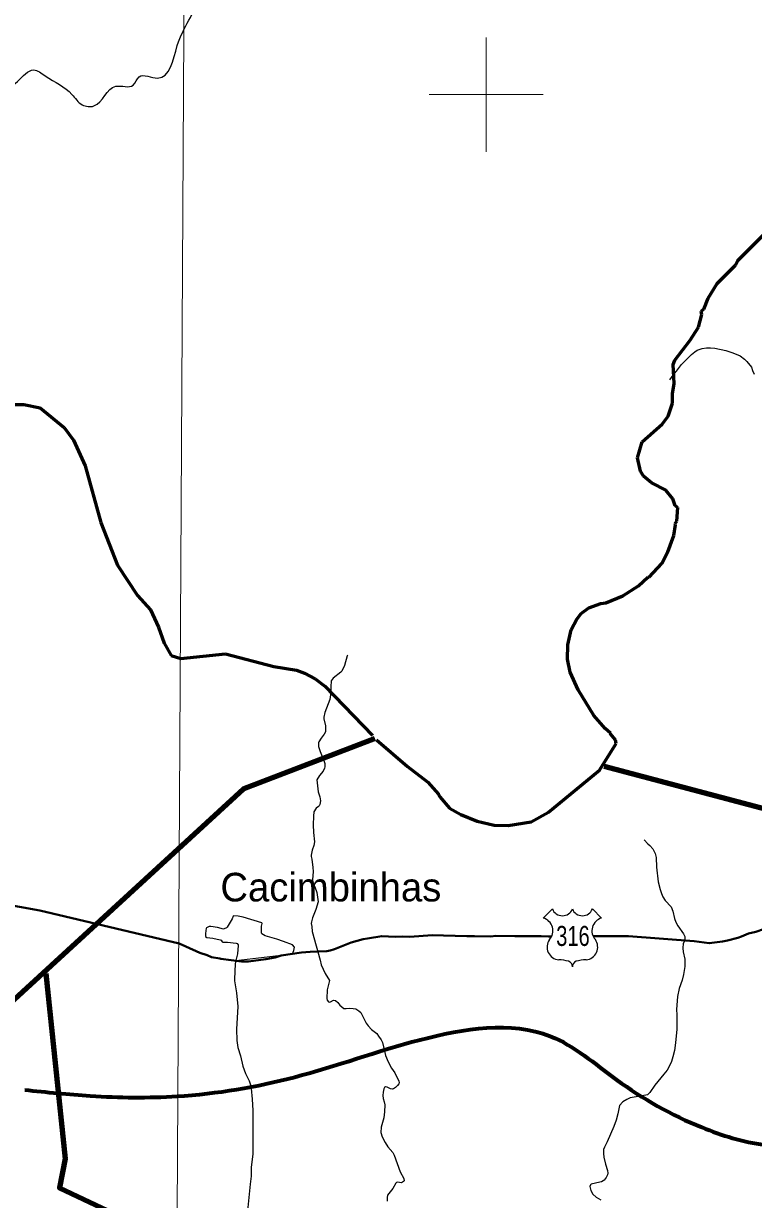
# Model space of a CAD drawing. Extents: x 553962 to 842807, y 8883888 to 9032388.
# Drawn here: x 716906 to 729677, y 8955681 to 8976242 of the extents above; entities that cross this region are included whole.
import ezdxf
from ezdxf.enums import TextEntityAlignment as Align

# ---------------------------------------------------------------- set-up
doc = ezdxf.new("R2010")
doc.units = 0
doc.header["$LTSCALE"] = 200
doc.linetypes.add('LONG_DASH_SHORT_DASH', pattern=[9.9, 6, -1.2, 1.5, -1.2])
for name, color, linetype, lineweight in [('1', 7, 'Continuous', 13), ('12', 7, 'Continuous', 25), ('2', 7, 'Continuous', 13), ('21', 7, 'Continuous', 25), ('24', 7, 'Continuous', 25), ('48', 7, 'Continuous', 25), ('51', 7, 'Continuous', 70), ('7', 7, 'LONG_DASH_SHORT_DASH', 60), ('9', 7, 'Continuous', 90)]:
    doc.layers.add(name, color=color, linetype=linetype, lineweight=lineweight)
doc.layers.add('41', color=7, linetype='Continuous')

msp = doc.modelspace()

# ---------------------------------------------------------------- linework, layer by layer
at = {"layer": '1'}
msp.add_lwpolyline([(719978.9, 9023574.5), (719561.6, 8949232.2), (719215.6, 8890710.6)], dxfattribs=at)
at = {"layer": '12', "lineweight": 40}
for points in [[(710551.5, 8961397.1), (711177.1, 8961501.2), (712016, 8961727.1), (712359, 8961724.2), (713550.7, 8961508.2), (716056.5, 8960938), (717193.5, 8960736.2), (719630.3, 8960157.3)], [(727488.2, 8960282.3), (728636.4, 8960199.6), (728903.4, 8960161.8), (729137.1, 8960189.3), (729219.7, 8960208.1), (729401, 8960258.8), (729465.4, 8960280.4), (729590.6, 8960330), (729719.4, 8960363), (729852.5, 8960406), (729969, 8960418.2), (730064.3, 8960434.8), (730362.8, 8960475.9), (730505.9, 8960510.9), (731000.5, 8960614.4), (731116.1, 8960622.6), (731172.1, 8960636.4), (731339.7, 8960662.3), (731644.2, 8960700.6)], [(721922.9, 8960009), (722213.7, 8960025.4), (722269.8, 8960036.4), (722349.1, 8960058.4), (722636.1, 8960173.1), (722845.7, 8960234.4), (722922.5, 8960243.5), (723174, 8960287.2), (723408.1, 8960273.8), (723541.7, 8960277.9), (723662.4, 8960276.1), (724053.4, 8960301.3), (724251.5, 8960299.1), (724661.8, 8960282.6), (724797.4, 8960284.4), (725081.1, 8960280.5), (725171.8, 8960288.1), (725504.3, 8960282.4), (725962.1, 8960286.2), (726091.1, 8960280.3), (726144.9, 8960281.9)], [(726871.4, 8960282.4), (727184.2, 8960282.3), (727488.2, 8960282.3)], [(719630.3, 8960157.3), (719924.9, 8960025), (719991.1, 8959995.2), (720116.1, 8959954.9), (720192.2, 8959919.6), (720337.5, 8959893.8), (720356.6, 8959891.3)], [(721309.9, 8959913.9), (721410.9, 8959945.9), (721766.8, 8959996.8), (721847.5, 8960004.7), (721922.9, 8960009)], [(720356.6, 8959891.3), (720717.1, 8959843.9), (720842.5, 8959844.2), (721142.7, 8959881.7), (721309.9, 8959913.9)]]:
    msp.add_lwpolyline(points, dxfattribs=at)
at = {"layer": '12'}
msp.add_lwpolyline([(720615.2, 8959855.5), (720600.9, 8959695.2), (720597, 8959505.1), (720630.5, 8959292.2), (720652.8, 8959055), (720632.1, 8958659.5), (720635, 8958462), (720656.1, 8958337.2), (720700.8, 8958191.8), (720743.2, 8958010.9), (720791.1, 8957885.8), (720852.6, 8957752.9), (720877.2, 8957688.2), (720888, 8957623.8), (720908.9, 8957434.4), (720919.8, 8957236.9), (720915.8, 8956822.8), (720917.5, 8956475.5), (720890.2, 8956243.7), (720885.8, 8956166.3), (720886.8, 8956088.9), (720868.9, 8955947.1), (720826.5, 8955484.8)], dxfattribs=at)
at = {"layer": '2'}
for p, q in [((725000, 8974000), (725000, 8976000)), ((724000, 8975000), (726000, 8975000))]:
    msp.add_line(p, q, dxfattribs=at)
at = {"layer": '21'}
for points in [[(721081.2, 8960508.1), (721077.4, 8960519.1), (720747.7, 8960615.2), (720662.9, 8960634.1), (720587.2, 8960643), (720575.8, 8960636.9), (720556, 8960586.9), (720470.6, 8960443.6), (720458.9, 8960430), (720418.1, 8960410.7), (720402.2, 8960408.3), (720301.9, 8960437.2), (720181, 8960453.2), (720156.1, 8960451.2), (720109.1, 8960428.1), (720098.9, 8960418.5), (720097.9, 8960382.4), (720087.7, 8960324.8), (720086.7, 8960296.8), (720091.3, 8960280.8), (720111.5, 8960263.6), (720216.2, 8960251.9), (720344.2, 8960222.5), (720362.4, 8960214), (720382.8, 8960188), (720394.4, 8960180.7), (720474.7, 8960182.3), (720628.9, 8960163.3), (720641.9, 8960157.8), (720658.4, 8960133.9), (720662.8, 8960119.5), (720650.8, 8959977.9), (720618.4, 8959856.9), (721612.4, 8959974.7)], [(721612.4, 8959974.7), (721632.5, 8960032.7), (721644.1, 8960093.2), (721614, 8960131.4), (721452.9, 8960193.9), (721340.2, 8960231.7), (721132.5, 8960290.7), (721078, 8960323.4), (721072, 8960337.7), (721069.2, 8960462.3), (721081.2, 8960508.1)]]:
    msp.add_lwpolyline(points, dxfattribs=at)
at = {"layer": '24'}
for points in [[(728214.3, 8970014.3), (728272, 8970092.8), (728331.6, 8970162.7), (728417.4, 8970282.5), (728594.8, 8970457.4), (728648.4, 8970499.8), (728691.9, 8970528.1), (728779.9, 8970559.1)], [(728779.9, 8970559.1), (728852.1, 8970572.7), (728924.3, 8970573), (729000.6, 8970564.2), (729191.8, 8970527), (729315.4, 8970483.8), (729446.4, 8970430), (729519.7, 8970374), (729562.9, 8970331.7), (729643.8, 8970234.4), (729657.8, 8970174.1), (729686.6, 8970110.8)], [(722575.5, 8965195.4), (722571, 8965187.9), (722519, 8965016.7), (722474.9, 8964918.2), (722459.2, 8964901.6), (722323.5, 8964797.9), (722290.5, 8964747.2), (722279.7, 8964646.8), (722281, 8964566), (722277.5, 8964502.2), (722266.5, 8964421.5), (722176.2, 8964195.9), (722157.5, 8964115.2), (722160.4, 8964087.6), (722187, 8963962.1), (722189.1, 8963859.1), (722167.7, 8963817.5), (722110.5, 8963747.7), (722070.3, 8963681.7), (722063.8, 8963664.4), (722068.1, 8963601.1), (722094, 8963516.1), (722162.6, 8963358.1), (722176.2, 8963303.1), (722177, 8963244), (722173.6, 8963223), (722150.4, 8963167.1), (722082.2, 8963092.3), (722039.2, 8963018), (722060.5, 8962810.2), (722090.5, 8962720.7), (722103.1, 8962648.5), (722089.6, 8962588.8), (722078.8, 8962562.8), (722066.8, 8962550.6), (722025.2, 8962521.8), (721986.8, 8962458), (721978, 8962385), (721975.3, 8962231.7), (721979, 8962096), (721995.3, 8961934.2), (721985.8, 8961870.2), (721954.4, 8961789.1)], [(727765.8, 8961970.3), (727825.8, 8961899), (727865.1, 8961870.8), (727914.4, 8961812.9), (727928.9, 8961790.8), (727957, 8961730.6), (727973.7, 8961658.3), (727982.1, 8961491.7), (728008.3, 8961232.6), (728042.5, 8961100.9), (728042.5, 8961100.9)], [(721954.4, 8961789.1), (721939, 8961701.5), (721940.5, 8961675.6), (721951.9, 8961632), (721968.9, 8961483.5), (721970.5, 8961415.5), (721961.3, 8961271), (721974.8, 8961199.1), (722002.5, 8961147.9), (722036.1, 8961049.7), (722059, 8960887.1), (722022.2, 8960752.4), (721958.8, 8960603.3), (721941.3, 8960535.4), (721939.8, 8960504.4), (721952, 8960451.2), (721953.6, 8960363.9)], [(728042.5, 8961100.9), (728066.8, 8961029.4), (728091.6, 8960973.5), (728132.1, 8960907.8), (728236.6, 8960797.5), (728265.1, 8960722.4), (728295.7, 8960595), (728319, 8960531.3), (728352.9, 8960467.6), (728449.6, 8960324.9), (728474.6, 8960281.8), (728477.4, 8960259.1), (728473.9, 8960208), (728448.7, 8960159), (728438.4, 8960076.1), (728447.6, 8960012.3), (728475.3, 8959880.6), (728477.7, 8959816.9), (728475.3, 8959753.2), (728452.1, 8959613.4), (728430.3, 8959518.6), (728374.1, 8959370.4), (728347.8, 8959231.5), (728331.8, 8959004.4), (728331.8, 8959004.4), (728335.5, 8958911.7), (728334.3, 8958656.7), (728310.4, 8958418), (728292.8, 8958286.4), (728267.6, 8958175.1), (728241.7, 8958095.1), (728211.8, 8958027.2), (728164.6, 8957944.8), (728110.8, 8957873.6), (728053, 8957810), (727953.2, 8957682.5), (727865.8, 8957554.2), (727836.3, 8957521.6), (727822.7, 8957513.3), (727793.9, 8957504.8), (727522, 8957455.7), (727461.9, 8957429.1), (727393.2, 8957387.5), (727330.4, 8957324.7), (727300.9, 8957176.3), (727274.3, 8957069.5), (727235.3, 8956955.2), (727115.7, 8956689.6), (727067.7, 8956593.8), (727054.2, 8956553.9), (727051.8, 8956483.4), (727060.3, 8956419.9), (727085.9, 8956300.9), (727122.2, 8956185.9), (727127.8, 8956143.5), (727122.6, 8956114.6), (727099.9, 8956065), (727062.7, 8956016.1), (727045.7, 8956009.6), (727016.4, 8955987.1), (726986.5, 8955986.3)], [(721953.6, 8960363.9), (722093.6, 8959865.1), (722115.4, 8959783), (722181.9, 8959629.9), (722261.1, 8959510.9)], [(722261.1, 8959510.9), (722232.9, 8959419.5), (722220.1, 8959349.1), (722211.4, 8959197.2), (722220.3, 8959168.5), (722243.5, 8959138), (722256, 8959132), (722279.2, 8959136), (722330.7, 8959164.3), (722365.7, 8959160.8), (722402.2, 8959127.6), (722442.3, 8959076.5), (722509.3, 8959021.4), (722549.7, 8959017.6), (722615.2, 8959023.5), (722670.4, 8959021.7), (722718.1, 8959012.5), (722774.8, 8958976.9), (722805.5, 8958948), (722900.4, 8958766.3), (722936.6, 8958715.7), (722995.9, 8958654.5), (723087, 8958581.5), (723116.2, 8958534.7)], [(723116.2, 8958534.7), (723162.6, 8958473.2), (723183.6, 8958425.5), (723238.3, 8958197.1), (723282.7, 8958086.6), (723342.1, 8957976.2), (723399.4, 8957895.1), (723474.7, 8957752.1), (723479.7, 8957724.8), (723473.3, 8957704.3), (723449.9, 8957676.3), (723412.8, 8957642), (723376.2, 8957617.7), (723360.7, 8957612.8), (723327.5, 8957613.9), (723266.1, 8957642.9), (723240.8, 8957648.2), (723221.2, 8957638.1), (723207.2, 8957613.1), (723195.8, 8957555.1), (723193.7, 8957499.8), (723199.5, 8957448.4), (723216.1, 8957389.2), (723224.3, 8957337.8), (723222.4, 8957215.7), (723211.1, 8957109.1), (723161.2, 8956943.2), (723155.2, 8956854.5), (723178.4, 8956777.7), (723231.8, 8956676.2), (723280.5, 8956599.2), (723364.6, 8956500.5), (723389.3, 8956454.5), (723495.1, 8956163.2), (723557.2, 8956045.2), (723565.7, 8956009), (723554.2, 8955994.3)], [(723554.2, 8955994.3), (723554.2, 8955994.3), (723519.5, 8955974.1), (723447.7, 8955984.5), (723432.7, 8955980), (723418, 8955965.8), (723364.6, 8955871.3), (723272.5, 8955754.9), (723268.2, 8955716.3), (723268.6, 8955650.3)], [(726986.5, 8955986.3), (726837.9, 8955949.1), (726825, 8955939.5), (726814.2, 8955910.4), (726817.4, 8955886), (726830.9, 8955839.7), (726865, 8955775.8), (726924.5, 8955721.1), (727005.9, 8955674.6)]]:
    msp.add_lwpolyline(points, dxfattribs=at)
msp.add_spline([(715037, 8973071.8), (715705.1, 8973746.2), (715968.5, 8974273.5), (716313.1, 8974881.9), (716799.5, 8975226.6), (717083.2, 8975429.4), (717285.9, 8975328), (717752, 8975003.5), (717934.4, 8974821), (718137.1, 8974800.7), (718522.2, 8975145.5), (718826.2, 8975165.8), (718927.5, 8975307.7), (719251.8, 8975287.5), (719596.3, 8975855.3), (719799, 8976301.5), (720042.2, 8976686.8), (720771.8, 8977072.1), (721197.4, 8977051.8), (721481.2, 8977356), (721987.8, 8977396.6), (722291.8, 8977356), (722514.8, 8977639.9), (722859.3, 8978086.1), (723244.4, 8978309.2), (723548.4, 8978795.9), (723507.9, 8979566.5), (723426.8, 8979749.1), (723730.8, 8980235.8), (724115.9, 8980418.3), (724501, 8980803.6), (724886, 8981067.2), (724886, 8981594.5), (724865.8, 8981939.3), (725068.4, 8982385.5), (725169.8, 8982831.6), (725331.9, 8983216.9), (725311.6, 8983582), (725473.8, 8983825.3), (725696.7, 8983987.6), (725777.8, 8984433.7), (725858.8, 8984636.5), (726183.1, 8984636.5), (726162.8, 8984920.5), (726284.5, 8985163.8), (726588.5, 8985569.4), (726993.8, 8986056.1), (726770.9, 8986299.5), (726466.9, 8986238.7), (726264.2, 8986340.1), (726527.7, 8986563.1), (726487.1, 8986745.7), (726770.9, 8986907.9), (727155.9, 8987090.4), (727297.8, 8987171.5), (727338.3, 8987496), (727581.6, 8987698.8), (727743.7, 8987921.9), (727905.8, 8988084.1), (728068, 8988408.6), (728351.7, 8988510), (728453, 8988814.2), (728655.7, 8988854.8), (728676, 8989098.1), (728898.9, 8989260.4), (729121.8, 8989260.4), (729284, 8989037.3), (729527.2, 8988733.1), (729750.1, 8988712.8), (729973.1, 8988834.5), (729993.3, 8988753.4), (730054.1, 8988530.3), (730135.2, 8988469.4), (730358.1, 8988469.4), (730459.5, 8988408.6), (730702.7, 8988489.7), (730702.7, 8988611.4), (730885.1, 8988652), (731067.5, 8988469.4), (731168.8, 8988347.8), (731472.8, 8988368), (731736.3, 8988631.7), (731857.9, 8988834.5), (732222.7, 8988814.2), (732324, 8989017), (732506.4, 8989138.7), (732547, 8989300.9), (732851, 8989402.3), (733073.9, 8989382), (733114.4, 8989666), (733215.8, 8989848.5)], degree=3, dxfattribs=at)
at = {"layer": '48'}
for p, q in [((725998.7, 8960602), (726158.6, 8960761.9)), ((726857.9, 8960761.9), (727017.9, 8960602))]:
    msp.add_line(p, q, dxfattribs=at)
for centre, radius, start, end in [((726333.4, 8960828.9), 187.2, 200.95927, 339.04073), ((726683.1, 8960828.9), 187.2, 200.95927, 339.04073), ((725936.6, 8960380.1), 230.3, 317.5721, 74.36886), ((727079.9, 8960380.1), 230.3, 105.62774, 222.4279), ((726290.1, 8960095), 224.7, 144.73733, 264.65778), ((726726.4, 8960095), 224.7, 275.34222, 35.26267), ((726268.2, 8959281.5), 589.7, 72.89371, 89.90057), ((726413.9, 8959754.9), 94.4, 357.69345, 72.92955), ((726602.6, 8959754.9), 94.4, 107.07045, 182.30655), ((726748.4, 8959281.5), 589.7, 90.09943, 107.10629)]:
    msp.add_arc(centre, radius, start, end, dxfattribs=at)
at = {"layer": '51'}
msp.add_spline([(716926.2, 8957598.1), (718074.6, 8957493.8), (719594.6, 8957486.8), (721652.8, 8957821.8), (723844.6, 8958473.8), (726122.5, 8958536.9), (727274.9, 8957780.4), (728772.1, 8956943.2), (729868.6, 8956635.9), (731465.1, 8956666.3)], degree=3, dxfattribs=at)
at = {"layer": '7'}
for points in [[(728775.4, 8971157.2), (728762.8, 8971215.3), (728807.7, 8971247.8), (728882.9, 8971442.9), (729041.4, 8971697.8), (729364.5, 8972018.1), (729404.2, 8972096.7), (730321.7, 8973018.8)], [(719658.3, 8965140.1), (720442, 8965220.3), (721288, 8965002.1), (721680.5, 8964933.5), (721820.1, 8964881.9), (722005.8, 8964784.1), (722178.5, 8964657), (723083.4, 8963715.2), (723625.8, 8963254.3), (723977.8, 8962977.1), (724168.2, 8962768.7), (724186.8, 8962722.9), (724359.5, 8962523.2), (724559.4, 8962414.2), (724841.1, 8962296.1), (725141, 8962223.5), (725386.8, 8962222.5), (725788.6, 8962283.2), (726090.3, 8962454.2), (726984.4, 8963189.7), (727272.9, 8963654), (727265.1, 8963720.5), (727171.4, 8963825.9), (727177.2, 8963835.7), (727083.5, 8963916.6), (726881.4, 8964145.8), (726607, 8964591.8), (726472.1, 8964903.4), (726424.9, 8965128.6), (726428, 8965378.3), (726489.2, 8965641.2), (726585.3, 8965827.1), (726663.7, 8965928.8), (726797, 8966026.6), (727004.8, 8966100.9), (727095.2, 8966112.8), (727389.2, 8966234.1), (727665.8, 8966411.4), (727830.4, 8966559.9), (727853.4, 8966559.4), (728073.8, 8966803.2), (728177.3, 8967005.8), (728281, 8967292.8), (728314.3, 8967479.3), (728306, 8967500.6), (728333.7, 8967541.7), (728350.7, 8967781.6), (728305.9, 8967811.8), (728268.5, 8967931), (728143.1, 8968083.6), (727891.6, 8968208.7), (727752.6, 8968328.3), (727699.6, 8968412.7), (727644.7, 8968647.4), (727727.1, 8968929.1), (728078.2, 8969238.6), (728184.2, 8969376), (728262.5, 8969602.8), (728262.6, 8969767.2), (728287.9, 8969948.7), (728268.9, 8970282.4), (728302.9, 8970356.4), (728566.6, 8970704.3), (728713.2, 8970930.1), (728775.4, 8971157.2)], [(714387.4, 8969902.2), (714562.6, 8969724), (714791.2, 8969580.7), (715019.8, 8969437.3), (715266.3, 8969329.2), (715566.5, 8969291.3), (716240, 8969497.5), (716452.6, 8969548.7), (716647.3, 8969582.3), (716912.5, 8969580.1), (717194.9, 8969524.6), (717616.1, 8969176.7), (717779.5, 8968954.6), (717981.6, 8968510.6), (718255.9, 8967518.7), (718550, 8966774), (718899, 8966240.8), (719126.6, 8965991.5), (719265.4, 8965689.9), (719369.1, 8965406.3), (719491, 8965193.2), (719658.3, 8965140.1)]]:
    msp.add_lwpolyline(points, dxfattribs=at)
at = {"layer": '9'}
msp.add_line((738230.2, 8960292.9), (727062.8, 8963254.1), dxfattribs=at)
for points in [[(705081.2, 8958366.8), (705509.2, 8948874.2), (720755.9, 8962863.6), (723053.6, 8963740.6)], [(717295.3, 8959630.3), (717636.9, 8956393.6), (717537.2, 8955887), (718376.1, 8955487), (718808.6, 8955185.8), (719472.1, 8954177.6), (719984.6, 8952814.2), (721077.3, 8952390.4), (721486.8, 8951456.6), (721666.8, 8950799.8), (721718.4, 8950547.1), (727920.4, 8947850.3), (733274.5, 8948007.9), (737635.8, 8948628.8)]]:
    msp.add_lwpolyline(points, dxfattribs=at)

# ---------------------------------------------------------------- texts
at = {"layer": '41'}
msp.add_text('Cacimbinhas', height=500, dxfattribs=at).set_placement((720350.3, 8960892.5))
at = {"layer": '48', "width": 0.75}
msp.add_text('316', height=350, dxfattribs=at).set_placement((726518.2, 8960114.2), align=Align.CENTER)

doc.saveas('drawing.dxf')
